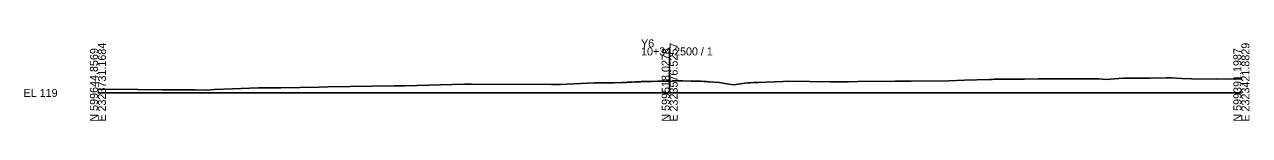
# Model space of a CAD drawing. Extents: x -26 to 3203, y -10 to 2019.
# Drawn here: x 2774.3 to 3202.8, y -9.7 to 18.7 of the extents above; entities that cross this region are included whole.
import ezdxf

# ---------------------------------------------------------------- set-up
doc = ezdxf.new("R2010")
doc.units = 0
for name, color, linetype in [('Exist CMT Pavement', 7, 'Continuous'), ('Exist Cross Section Cell', 7, 'Continuous'), ('Exist XS Center Line Elevation Label', 7, 'Continuous'), ('Exist XS Ground Line', 7, 'Continuous'), ('Prop XS Earthwork Shape', 7, 'Continuous')]:
    doc.layers.add(name, color=color, linetype=linetype)

msp = doc.modelspace()

# ---------------------------------------------------------------- linework, layer by layer
at = {"layer": 'Exist CMT Pavement'}
for points in [[(2999.9, 4.13), (2999.9, 4.23), (3000, 4.23), (3000, 4.13)], [(3000, 4.13), (3000, 4.23), (3000.1, 4.23), (3000.1, 4.12)]]:
    msp.add_lwpolyline(points, dxfattribs=at)
at = {"layer": 'Exist Cross Section Cell'}
for p, q in [((3000, 0), (3000, 15.87)), ((2800, 0), (3000, 0)), ((3000, 0), (3200, 0))]:
    msp.add_line(p, q, dxfattribs=at)
at = {"layer": 'Exist XS Ground Line'}
msp.add_lwpolyline([(2800, 1.3), (2804.72, 1.22), (2805.37, 1.28), (2822.62, 1.11), (2824.12, 1.07), (2827.55, 1.13), (2831.75, 1.1), (2834.05, 1.06), (2838.42, 1.01), (2840.64, 1.2), (2847.05, 1.39), (2856.14, 1.74), (2860.54, 1.8), (2864.01, 1.8), (2877.37, 2.06), (2880.47, 2.08), (2903.74, 2.49), (2905.72, 2.51), (2907.36, 2.52), (2928.28, 3.05), (2929.48, 3.05), (2930.55, 3.07), (2958.67, 2.93), (2960.37, 2.96), (2961.7, 2.91), (2973.73, 3.51), (2974.52, 3.52), (2980.44, 3.53), (2983.17, 3.68), (2984.91, 3.69), (2985.27, 3.71), (2985.69, 3.73), (2986.23, 3.75), (2986.92, 3.78), (2987.85, 3.82), (2989.16, 3.89), (2989.82, 3.92), (2990.16, 3.93), (2991.22, 3.94), (2991.94, 3.96), (2993.9, 4.02), (2995.8, 4.07), (2996.58, 4.09), (2998.36, 4.13), (2999.27, 4.15), (3000.24, 4.12), (3000.72, 4.01), (3001.01, 4.18), (3001.95, 4.18), (3003.52, 4.18), (3004.63, 4.18), (3007.55, 4.14), (3010.55, 4.08), (3010.98, 4.05), (3012.1, 3.99), (3012.87, 3.95), (3013.44, 3.92), (3013.89, 3.89), (3017.35, 3.61), (3020.74, 3.07), (3022.43, 2.82), (3023.97, 3.01), (3027.27, 3.53), (3028.22, 3.56), (3029.35, 3.59), (3031.11, 3.67), (3033.66, 3.78), (3039.76, 3.98), (3041.73, 4.13), (3056.27, 3.87), (3062.51, 3.92), (3065.84, 3.98), (3078.85, 4.05), (3084.54, 4.1), (3097.71, 4.26), (3103.1, 4.42), (3111.83, 4.73), (3112.87, 4.74), (3113.39, 4.75), (3124.12, 4.84), (3128.97, 4.86), (3136.15, 4.88), (3144.16, 4.93), (3146.79, 4.91), (3149.98, 4.92), (3152.67, 4.74), (3155.54, 4.86), (3158.75, 5.14), (3162.58, 5.16), (3165.72, 5.16), (3168.02, 5.19), (3173.85, 5.24), (3175.56, 5.29), (3179.15, 5.05), (3182.52, 4.94), (3191.14, 4.83), (3194.41, 4.86), (3200, 4.85)], dxfattribs=at)
at = {"layer": 'Prop XS Earthwork Shape'}
for points in [[(3000, 4.23), (3000, 4.13), (2999.9, 4.13), (2999.9, 4.23)], [(3000, 4.13), (3000.1, 4.12), (3000.1, 4.23), (3000, 4.23)]]:
    msp.add_lwpolyline(points, close=True, dxfattribs=at)

# ---------------------------------------------------------------- texts
at = {"layer": 'Exist Cross Section Cell'}
for s, p in [('E 2323731.1684', (2802.8, -10)), ('E 2323576.5257', (3002.8, -10)), ('E 2323421.8829', (3202.8, -10)), ('N 599644.8569', (2800, -10)), ('N 599518.0278', (3000, -10)), ('N 599391.1987', (3200, -10))]:
    msp.add_text(s, height=2.8, rotation=90, dxfattribs=at).set_placement(p)
for s, p in [('Y6', (2990, 15.87)), ('10+34.2500 / 1', (2990, 13.07)), ('EL 119', (2774, -1.4))]:
    msp.add_text(s, height=2.8, dxfattribs=at).set_placement(p)
at = {"layer": 'Exist XS Center Line Elevation Label'}
msp.add_text('123.16', height=0.2, dxfattribs=at).set_placement((2999.65, 2.16))

doc.saveas('drawing.dxf')
